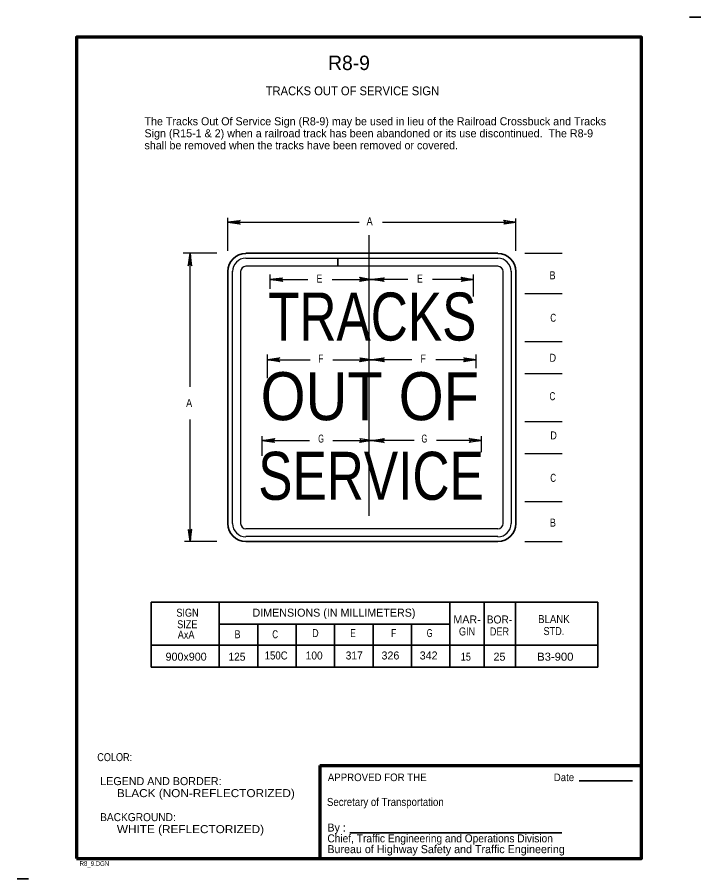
# Model space of a CAD drawing. Extents: x -209486.33 to -209486.116, y -162055.884 to -162055.615.
import ezdxf
from ezdxf.enums import TextEntityAlignment as Align

# ---------------------------------------------------------------- set-up
doc = ezdxf.new("R2010")
doc.units = 0
doc.header["$LTSCALE"] = 0.001
doc.linetypes.add('LONG_DASH_SHORT_DASH', pattern=[9.9, 6, -1.2, 1.5, -1.2])
for name, color, linetype, lineweight in [('1', 7, 'Continuous', 25), ('3', 7, 'Continuous', 35), ('5', 7, 'Continuous', 25)]:
    doc.layers.add(name, color=color, linetype=linetype, lineweight=lineweight)

msp = doc.modelspace()

# ---------------------------------------------------------------- linework, layer by layer
at = {"layer": '1', "lineweight": 35}
for p, q in [((-209486.116125, -162055.615), (-209486.119625, -162055.615)), ((-209486.154125, -162055.8535), (-209486.1375, -162055.8535)), ((-209486.22575, -162055.86975), (-209486.1595, -162055.86975)), ((-209486.326125, -162055.884125), (-209486.329625, -162055.884125))]:
    msp.add_line(p, q, dxfattribs=at)
at = {"layer": '1'}
for p, q in [((-209486.262375, -162055.773125), (-209486.262375, -162055.694375)), ((-209486.259875, -162055.694375), (-209486.259875, -162055.773125)), ((-209486.177875, -162055.773125), (-209486.177875, -162055.694375)), ((-209486.175375, -162055.694375), (-209486.175375, -162055.773125)), ((-209486.25825, -162055.77475), (-209486.1795, -162055.77475)), ((-209486.1795, -162055.77725), (-209486.25825, -162055.77725))]:
    msp.add_line(p, q, dxfattribs=at)
at = {"layer": '1', "lineweight": 70}
for q in [(-209486.134625, -162055.84875), (-209486.235125, -162055.87775)]:
    msp.add_line((-209486.235125, -162055.84875), q, dxfattribs=at)
msp.add_lwpolyline([(-209486.311125, -162055.87775), (-209486.134625, -162055.87775), (-209486.134625, -162055.62125), (-209486.311125, -162055.62125)], close=True, dxfattribs=at)
at = {"layer": '1'}
for points in [[(-209486.26025, -162055.6795), (-209486.260375, -162055.67925), (-209486.263875, -162055.679), (-209486.26025, -162055.6795), (-209486.26, -162055.679625), (-209486.263875, -162055.679), (-209486.260375, -162055.678875), (-209486.26025, -162055.678625), (-209486.263875, -162055.679), (-209486.26, -162055.6785), (-209486.26025, -162055.678625)], [(-209486.1775, -162055.678625), (-209486.177375, -162055.678875), (-209486.173875, -162055.679), (-209486.1775, -162055.678625), (-209486.177625, -162055.678375), (-209486.173875, -162055.679), (-209486.177375, -162055.67925), (-209486.1775, -162055.6795), (-209486.173875, -162055.679), (-209486.177625, -162055.679625), (-209486.1775, -162055.6795)], [(-209486.27525, -162055.692375), (-209486.2755, -162055.69225), (-209486.275625, -162055.68875), (-209486.27525, -162055.692375), (-209486.275125, -162055.692625), (-209486.275625, -162055.68875), (-209486.275875, -162055.69225), (-209486.276125, -162055.692375), (-209486.275625, -162055.68875), (-209486.27625, -162055.692625), (-209486.276125, -162055.692375)], [(-209486.25825, -162055.69025), (-209486.2295, -162055.69025), (-209486.2295, -162055.69275), (-209486.25825, -162055.69275)], [(-209486.1795, -162055.69275), (-209486.2295, -162055.69275), (-209486.2295, -162055.69025), (-209486.1795, -162055.69025)], [(-209486.246875, -162055.697375), (-209486.247125, -162055.697125), (-209486.250625, -162055.696875), (-209486.246875, -162055.697375), (-209486.24675, -162055.6975), (-209486.250625, -162055.696875), (-209486.247125, -162055.69675), (-209486.246875, -162055.6965), (-209486.250625, -162055.696875), (-209486.24675, -162055.696375), (-209486.246875, -162055.6965)], [(-209486.2225, -162055.6965), (-209486.222375, -162055.69675), (-209486.218875, -162055.696875), (-209486.2225, -162055.6965), (-209486.222625, -162055.69625), (-209486.218875, -162055.696875), (-209486.222375, -162055.697125), (-209486.2225, -162055.697375), (-209486.218875, -162055.696875), (-209486.222625, -162055.6975), (-209486.2225, -162055.697375)], [(-209486.21525, -162055.697375), (-209486.215375, -162055.697125), (-209486.218875, -162055.696875), (-209486.21525, -162055.697375), (-209486.215, -162055.6975), (-209486.218875, -162055.696875), (-209486.215375, -162055.69675), (-209486.21525, -162055.6965), (-209486.218875, -162055.696875), (-209486.215, -162055.696375), (-209486.21525, -162055.6965)], [(-209486.19075, -162055.6965), (-209486.190625, -162055.69675), (-209486.187125, -162055.696875), (-209486.19075, -162055.6965), (-209486.191, -162055.69625), (-209486.187125, -162055.696875), (-209486.190625, -162055.697125), (-209486.19075, -162055.697375), (-209486.187125, -162055.696875), (-209486.191, -162055.6975), (-209486.19075, -162055.697375)], [(-209486.247875, -162055.722375), (-209486.248, -162055.722125), (-209486.2515, -162055.722), (-209486.247875, -162055.722375), (-209486.247625, -162055.722625), (-209486.2515, -162055.722), (-209486.248, -162055.72175), (-209486.247875, -162055.7215), (-209486.2515, -162055.722), (-209486.247625, -162055.721375), (-209486.247875, -162055.7215)], [(-209486.2225, -162055.7215), (-209486.222375, -162055.72175), (-209486.218875, -162055.722), (-209486.2225, -162055.7215), (-209486.222625, -162055.721375), (-209486.218875, -162055.722), (-209486.222375, -162055.722125), (-209486.2225, -162055.722375), (-209486.218875, -162055.722), (-209486.222625, -162055.722625), (-209486.2225, -162055.722375)], [(-209486.21525, -162055.722375), (-209486.215375, -162055.722125), (-209486.218875, -162055.722), (-209486.21525, -162055.722375), (-209486.215, -162055.722625), (-209486.218875, -162055.722), (-209486.215375, -162055.72175), (-209486.21525, -162055.7215), (-209486.218875, -162055.722), (-209486.215, -162055.721375), (-209486.21525, -162055.7215)], [(-209486.189875, -162055.7215), (-209486.18975, -162055.72175), (-209486.18625, -162055.722), (-209486.189875, -162055.7215), (-209486.190125, -162055.721375), (-209486.18625, -162055.722), (-209486.18975, -162055.722125), (-209486.189875, -162055.722375), (-209486.18625, -162055.722), (-209486.190125, -162055.722625), (-209486.189875, -162055.722375)], [(-209486.249375, -162055.74775), (-209486.249625, -162055.7475), (-209486.253125, -162055.74725), (-209486.249375, -162055.74775), (-209486.24925, -162055.747875), (-209486.253125, -162055.74725), (-209486.249625, -162055.747125), (-209486.249375, -162055.746875), (-209486.253125, -162055.74725), (-209486.24925, -162055.746625), (-209486.249375, -162055.746875)], [(-209486.2225, -162055.74675), (-209486.222375, -162055.747125), (-209486.218875, -162055.74725), (-209486.2225, -162055.74675), (-209486.222625, -162055.746625), (-209486.218875, -162055.74725), (-209486.222375, -162055.747375), (-209486.2225, -162055.747625), (-209486.218875, -162055.74725), (-209486.222625, -162055.747875), (-209486.2225, -162055.747625)], [(-209486.21525, -162055.74775), (-209486.215375, -162055.7475), (-209486.218875, -162055.74725), (-209486.21525, -162055.74775), (-209486.215, -162055.747875), (-209486.218875, -162055.74725), (-209486.215375, -162055.747125), (-209486.21525, -162055.746875), (-209486.218875, -162055.74725), (-209486.215, -162055.746625), (-209486.21525, -162055.746875)], [(-209486.18825, -162055.74675), (-209486.188125, -162055.747125), (-209486.184625, -162055.74725), (-209486.18825, -162055.74675), (-209486.1885, -162055.746625), (-209486.184625, -162055.74725), (-209486.188125, -162055.747375), (-209486.18825, -162055.747625), (-209486.184625, -162055.74725), (-209486.1885, -162055.747875), (-209486.18825, -162055.747625)], [(-209486.276125, -162055.775125), (-209486.275875, -162055.77525), (-209486.275625, -162055.77875), (-209486.276125, -162055.775125), (-209486.27625, -162055.775), (-209486.275625, -162055.77875), (-209486.2755, -162055.77525), (-209486.27525, -162055.775125), (-209486.275625, -162055.77875), (-209486.275125, -162055.775), (-209486.27525, -162055.775125)]]:
    msp.add_lwpolyline(points, dxfattribs=at)
for centre, radius, start, end in [((-209486.258232, -162055.694423), 0.004125, 90, 180), ((-209486.179482, -162055.694423), 0.004125, 0, 90), ((-209486.258232, -162055.694423), 0.001625, 90, 180), ((-209486.179482, -162055.694423), 0.001625, 0, 90), ((-209486.258232, -162055.773173), 0.004125, 180, 270), ((-209486.258232, -162055.773173), 0.001625, 180, 270), ((-209486.179482, -162055.773173), 0.001625, 270, 0), ((-209486.179482, -162055.773173), 0.004125, 270, 0)]:
    msp.add_arc(centre, radius, start, end, dxfattribs=at)
at = {"layer": '3'}
for p, q in [((-209486.28775, -162055.79775), (-209486.14825, -162055.79775)), ((-209486.2665, -162055.79775), (-209486.2665, -162055.818)), ((-209486.1945, -162055.79775), (-209486.1945, -162055.818)), ((-209486.18375, -162055.797625), (-209486.18375, -162055.817875)), ((-209486.174, -162055.79775), (-209486.174, -162055.818)), ((-209486.14825, -162055.79775), (-209486.14825, -162055.818)), ((-209486.1945, -162055.804625), (-209486.2665, -162055.804625)), ((-209486.2545, -162055.804625), (-209486.2545, -162055.818)), ((-209486.2425, -162055.804625), (-209486.2425, -162055.818)), ((-209486.2305, -162055.804625), (-209486.2305, -162055.818)), ((-209486.2185, -162055.804625), (-209486.2185, -162055.818)), ((-209486.2065, -162055.804625), (-209486.2065, -162055.818)), ((-209486.28775, -162055.811125), (-209486.14825, -162055.811125))]:
    msp.add_line(p, q, dxfattribs=at)
msp.add_lwpolyline([(-209486.28775, -162055.79775), (-209486.28775, -162055.818), (-209486.14825, -162055.818)], dxfattribs=at)
at = {"layer": '5'}
for p, q in [((-209486.263875, -162055.688), (-209486.263875, -162055.677625)), ((-209486.263875, -162055.679), (-209486.222875, -162055.679)), ((-209486.2155, -162055.679), (-209486.173875, -162055.679)), ((-209486.173875, -162055.688), (-209486.173875, -162055.677875)), ((-209486.26725, -162055.68875), (-209486.27775, -162055.68875)), ((-209486.275625, -162055.7305), (-209486.275625, -162055.68875)), ((-209486.171125, -162055.68875), (-209486.159375, -162055.68875)), ((-209486.263875, -162055.773125), (-209486.263875, -162055.694375)), ((-209486.250625, -162055.699875), (-209486.250625, -162055.695375)), ((-209486.187125, -162055.70225), (-209486.187125, -162055.695375)), ((-209486.250625, -162055.696875), (-209486.238875, -162055.696875)), ((-209486.23125, -162055.696875), (-209486.218875, -162055.696875)), ((-209486.207625, -162055.696875), (-209486.218875, -162055.696875)), ((-209486.187125, -162055.696875), (-209486.199875, -162055.696875)), ((-209486.171125, -162055.70125), (-209486.159375, -162055.70125)), ((-209486.171125, -162055.71625), (-209486.159375, -162055.71625)), ((-209486.2515, -162055.72775), (-209486.2515, -162055.720375)), ((-209486.18625, -162055.724625), (-209486.18625, -162055.720375)), ((-209486.2515, -162055.722), (-209486.238125, -162055.722)), ((-209486.231, -162055.722), (-209486.218875, -162055.722)), ((-209486.206375, -162055.722), (-209486.218875, -162055.722)), ((-209486.18625, -162055.722), (-209486.198875, -162055.722)), ((-209486.171125, -162055.72625), (-209486.159375, -162055.72625)), ((-209486.275625, -162055.77875), (-209486.275625, -162055.740625)), ((-209486.171125, -162055.74125), (-209486.159375, -162055.74125)), ((-209486.253125, -162055.752), (-209486.253125, -162055.745875)), ((-209486.253125, -162055.74725), (-209486.238375, -162055.74725)), ((-209486.231, -162055.74725), (-209486.218875, -162055.74725)), ((-209486.205625, -162055.74725), (-209486.218875, -162055.74725)), ((-209486.184625, -162055.74725), (-209486.198625, -162055.74725)), ((-209486.184625, -162055.750875), (-209486.184625, -162055.745875)), ((-209486.171125, -162055.75125), (-209486.159375, -162055.75125)), ((-209486.171125, -162055.76625), (-209486.159375, -162055.76625)), ((-209486.26725, -162055.77875), (-209486.277375, -162055.77875)), ((-209486.171125, -162055.77875), (-209486.159375, -162055.77875))]:
    msp.add_line(p, q, dxfattribs=at)
at = {"layer": '5', "linetype": 'LONG_DASH_SHORT_DASH'}
msp.add_line((-209486.21975, -162055.77075), (-209486.21975, -162055.683125), dxfattribs=at)
at = {"layer": '5', "lineweight": 35}
for p, q in [((-209486.25825, -162055.68875), (-209486.1795, -162055.68875)), ((-209486.263875, -162055.773125), (-209486.263875, -162055.694375)), ((-209486.173875, -162055.773125), (-209486.173875, -162055.694375)), ((-209486.25825, -162055.77875), (-209486.1795, -162055.77875))]:
    msp.add_line(p, q, dxfattribs=at)
for centre, start, end in [((-209486.258232, -162055.694423), 90, 180), ((-209486.179482, -162055.694423), 0, 90), ((-209486.258232, -162055.773173), 180, 270), ((-209486.179482, -162055.773173), 270, 0)]:
    msp.add_arc(centre, 0.005625, start, end, dxfattribs=at)

# ---------------------------------------------------------------- texts
at = {"layer": '1'}
msp.add_text('R8-9', height=0.0045, dxfattribs=at).set_placement((-209486.226, -162055.6315), align=Align.CENTER)
for s, height, width, p in [('TRACKS OUT OF SERVICE SIGN', 0.00275, 0.95, (-209486.224937, -162055.639375)), ('TRACKS', 0.015, 0.8, (-209486.21875, -162055.716)), ('OUT OF', 0.015, 0.9, (-209486.2195, -162055.740875)), ('SERVICE', 0.015, 0.8, (-209486.219125, -162055.76575)), ('APPROVED FOR THE', 0.002375, 0.95, (-209486.217188, -162055.853625)), ('Date ', 0.002375, 0.95, (-209486.158438, -162055.853625))]:
    msp.add_text(s, height=height, dxfattribs=dict(at, width=width)).set_placement(p, align=Align.CENTER)
for s, height, width, p in [('COLOR:', 0.0025, 0.85, (-209486.304625, -162055.847375)), ('      BLACK (NON-REFLECTORIZED)', 0.0025, 1.1, (-209486.304625, -162055.858625)), ('Secretary of Transportation', 0.0025, 0.9, (-209486.232875, -162055.861375)), (' BACKGROUND:', 0.0025, 0.95, (-209486.304625, -162055.866125)), ('      WHITE (REFLECTORIZED)', 0.0025, 1.1, (-209486.304625, -162055.869875)), ('Chief, Traffic Engineering and Operations Division', 0.0025, 0.95, (-209486.23275, -162055.87275)), ('R8_9.DGN', 0.0015, 0.75, (-209486.310125, -162055.880125))]:
    msp.add_text(s, height=height, dxfattribs=dict(at, width=width)).set_placement(p)
for s, p in [(' LEGEND AND BORDER:', (-209486.304625, -162055.854875)), ('By :', (-209486.23275, -162055.869375)), ('Bureau of Highway Safety and Traffic Engineering', (-209486.23275, -162055.876125))]:
    msp.add_text(s, height=0.0025, dxfattribs=at).set_placement(p)
at = {"layer": '3'}
for s, p in [('The Tracks Out Of Service Sign (R8-9) may be used in lieu of the Railroad Crossbuck and Tracks', (-209486.289875, -162055.64875)), ('Sign (R15-1 & 2) when a railroad track has been abandoned or its use discontinued.  The R8-9', (-209486.289875, -162055.6525)), ('shall be removed when the tracks have been removed or covered.  ', (-209486.289875, -162055.65625))]:
    msp.add_text(s, height=0.0025, dxfattribs=at).set_placement(p)
for s, width, p in [('SIGN', 0.85, (-209486.276437, -162055.80225)), ('SIZE', 0.85, (-209486.2765, -162055.805875)), ('BOR-', 0.95, (-209486.179, -162055.804375)), ('BLANK', 0.9, (-209486.162, -162055.80425)), ('AxA', 0.85, (-209486.276875, -162055.809125)), ('B', 0.85, (-209486.260812, -162055.809)), ('C', 0.75, (-209486.249062, -162055.809)), ('D', 0.85, (-209486.2365, -162055.808625)), ('E', 0.8, (-209486.22475, -162055.808625)), ('F', 0.8, (-209486.212063, -162055.808625)), ('G', 0.7, (-209486.200812, -162055.808625)), ('GIN', 0.85, (-209486.189125, -162055.808125)), ('DER', 0.85, (-209486.179, -162055.808125)), ('STD.', 0.85, (-209486.162, -162055.808)), ('125', 0.95, (-209486.261, -162055.816)), ('150C', 0.9, (-209486.24875, -162055.815625)), ('100', 0.95, (-209486.236875, -162055.815625)), ('317', 0.95, (-209486.224375, -162055.815625)), ('15', 0.85, (-209486.1895, -162055.816)), ('B3-900', 1.05, (-209486.161562, -162055.816))]:
    msp.add_text(s, height=0.0025, dxfattribs=dict(at, width=width)).set_placement(p, align=Align.CENTER)
for s, p in [('DIMENSIONS (IN MILLIMETERS)', (-209486.230688, -162055.80225)), ('MAR-', (-209486.189125, -162055.804375)), ('900x900', (-209486.276875, -162055.816)), ('326', (-209486.213062, -162055.815625)), ('342', (-209486.201125, -162055.815625)), ('25', (-209486.179, -162055.816))]:
    msp.add_text(s, height=0.0025, dxfattribs=at).set_placement(p, align=Align.CENTER)
at = {"layer": '5'}
for s, width, p in [('A', 0.85, (-209486.2205, -162055.68)), ('E', 0.8, (-209486.236125, -162055.697875)), ('E', 0.8, (-209486.20475, -162055.697875)), ('B', 0.85, (-209486.163375, -162055.696875)), ('C', 0.75, (-209486.163125, -162055.710125)), ('F', 0.8, (-209486.235625, -162055.722875)), ('F', 0.8, (-209486.203625, -162055.722875)), ('D', 0.85, (-209486.163375, -162055.722625)), ('C', 0.75, (-209486.163375, -162055.734625)), ('A', 0.85, (-209486.276875, -162055.73675)), ('D', 0.85, (-209486.163125, -162055.746875)), ('G', 0.7, (-209486.235625, -162055.747875)), ('G', 0.7, (-209486.203375, -162055.747875)), ('C', 0.75, (-209486.163125, -162055.760125)), ('B', 0.85, (-209486.16325, -162055.774125))]:
    msp.add_text(s, height=0.0025, dxfattribs=dict(at, width=width)).set_placement(p)

doc.saveas('drawing.dxf')
